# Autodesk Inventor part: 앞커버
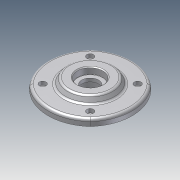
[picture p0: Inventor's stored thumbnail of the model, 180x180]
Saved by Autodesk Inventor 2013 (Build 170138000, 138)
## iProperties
Company: 한국ATC센터
Created: 2014-08
Part Number: 앞커버
Document SubType Name: Modeling
Designer: KYOUNG IL JANG
Density: 1 g/cm^3
Material: 일반
Mass: 89.0213 g
Surface Area: 231.959 cm^2
Volume: 89.0213 cm^3
Author: KYOUNG IL JANG
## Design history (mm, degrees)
sketch "스케치1"
  geometry: C1 r 30 at (0, 0) reference; A1 r 53.623 centre (0, -3.623) between (36.062, 36.062) and (-36.062, 36.062) reference; A2 r 53.623 centre (3.623, 0) between (-36.062, 36.062) and (-36.062, -36.062) reference; A3 r 53.623 centre (-3.623, 0) between (36.062, -36.062) and (36.062, 36.062) reference; A4 r 53.623 centre (0, 3.623) between (-36.062, -36.062) and (36.062, -36.062) reference; 1 further point
  node "참조9"
  node "참조14"
  node "참조15"
  node "참조16"
  node "참조17"
extrude "돌출1" new body sketch "스케치1" distance "d0" = 8; taper "d1" = 0 deg
sketch "스케치2"
  geometry: C1 r 30 at (0, 0); 1 further point
  constraints: 1 centre point, 1 coincident
  dimensions: "d2" = 60 diameter of C1
extrude "돌출2" join sketch "스케치2" distance "d3" = 7; taper "d4" = -30 deg
hole "구멍1" diameter "d7" = 20; stored, may be unused: countersink angle "d11" = 90 deg, drill point angle "d13" = 118 deg; dims "d5" = 10, "d6" = 10, "d8" = 6, "d9" = 30, "d10" = 8, "d12" = 20
sketch "스케치3"
  geometry: C1 r 1.621 at (28.284, 28.284) reference; C2 r 1.621 at (-28.284, 28.284) reference; C3 r 1.621 at (-28.284, -28.284) reference; C4 r 1.621 at (28.284, -28.284) reference; 1 further point
hole "구멍2" sketch "스케치3" at (28.284, 28.284), (28.284, -28.284), (-28.284, -28.284), (-28.284, 28.284) diameter "d14" = 4.5; stored, may be unused: countersink angle "d18" = 90 deg, drill point angle "d20" = 118 deg; dims "d15" = 6, "d16" = 8, "d17" = 4.4, "d19" = 20
extrude "돌출3" join sketch "스케치1" distance "d21" = 12; taper "d22" = 0 deg
hole "구멍3" diameter "d25" = 30; stored, may be unused: countersink angle "d29" = 90 deg, drill point angle "d31" = 0 deg; dims "d23" = 10, "d24" = 10, "d26" = 6, "d27" = 40, "d28" = 12, "d30" = 15
fillet "모깎기1" dims "d32" = 3, "d33" = 0.3
chamfer "모따기1" distance "d34" = 1; stored, may be unused: second distance "d35" = 2, angle "d36" = 45 deg
node "솔리드1"
node "참조10"
node "참조11"
node "참조12"
node "참조13"
